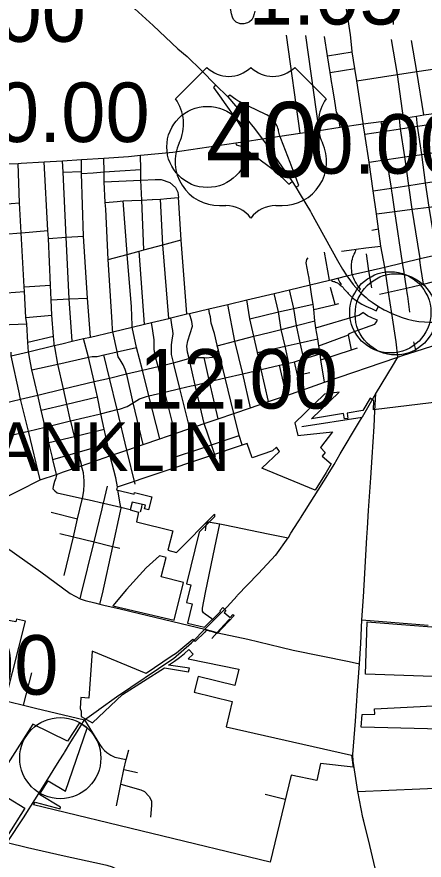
# Model space of a CAD drawing. Extents: x 1659811 to 1934326, y 644115 to 934867.
# Drawn here: x 1811230 to 1818761, y 699875 to 715463 of the extents above; entities that cross this region are included whole.
import ezdxf

# ---------------------------------------------------------------- set-up
doc = ezdxf.new("R2010")
doc.units = 0
for name, color, linetype in [('Default', 7, 'Continuous'), ('GM_X_City_Street', 7, 'Continuous'), ('GM_X_Corporation', 7, 'Continuous'), ('GM_X_County_Road', 7, 'Continuous'), ('GM_X_Interchange_Ramps', 7, 'Continuous'), ('GM_X_Interstate_Route', 7, 'Continuous'), ('GM_X_Township_Road', 7, 'Continuous'), ('GM_X_Township_Text', 7, 'Continuous'), ('GM_X_US_Route', 7, 'Continuous'), ('GM_X_US_Shield', 7, 'Continuous')]:
    doc.layers.add(name, color=color, linetype=linetype)

msp = doc.modelspace()

# ---------------------------------------------------------------- linework, layer by layer
at = {"layer": 'Default'}
for centre in [(1814753, 713058), (1818136, 710001), (1818235, 709964), (1812033, 701761)]:
    msp.add_circle(centre, 750, dxfattribs=at)
at = {"layer": 'GM_X_City_Street'}
for points in [[(1815632, 715569), (1815621, 715518), (1815602, 715455), (1815574, 715407), (1815531, 715370), (1815495, 715351), (1815424, 715332), (1815357, 715336), (1815288, 715363), (1815236, 715416), (1815215, 715459), (1815198, 715518), (1815177, 715654), (1815173, 715717)], [(1817633, 713505), (1817517, 714278), (1817480, 714507), (1817430, 714816), (1817428, 714828), (1817400, 715133), (1817342, 715495), (1817314, 715673)], [(1818194, 715322), (1818207, 715605)], [(1816466, 713313), (1816217, 715127)], [(1816823, 713365), (1816573, 715119)], [(1817054, 714231), (1817022, 714433), (1816973, 714743), (1816916, 715100)], [(1818382, 713593), (1818269, 714396), (1818157, 715046)], [(1818756, 713649), (1818628, 714451), (1818530, 715024)], [(1816973, 714743), (1817430, 714816)], [(1817517, 714278), (1818269, 714396), (1818628, 714451), (1819003, 714510), (1819276, 714553)], [(1817022, 714433), (1817480, 714507)], [(1817175, 713626), (1817170, 713652), (1817139, 713701), (1817108, 713905), (1817058, 714207), (1817054, 714231)], [(1817211, 713422), (1817176, 713623), (1817175, 713626)], [(1818978, 711164), (1818964, 711261), (1818854, 711948), (1818788, 712395), (1818717, 712921), (1818640, 713441), (1818617, 713626)], [(1817819, 712248), (1817745, 712775), (1817666, 713295), (1817636, 713485), (1817633, 713505)], [(1818169, 712211), (1818166, 712232), (1818156, 712299), (1818072, 712824), (1817995, 713343), (1817965, 713531)], [(1817995, 713343), (1818327, 713393), (1818640, 713441), (1819012, 713500), (1819390, 713554)], [(1818748, 710520), (1818701, 710832), (1818679, 710967), (1818688, 710994), (1818646, 711261), (1818537, 711906), (1818478, 712348), (1818404, 712874), (1818327, 713393), (1818303, 713580)], [(1817666, 713295), (1817995, 713343)], [(1817745, 712775), (1818072, 712824), (1818404, 712874), (1818717, 712921), (1819143, 712985), (1819468, 713033), (1819623, 713055)], [(1812589, 709545), (1812534, 710266), (1812465, 711412), (1812427, 712570), (1812425, 712607), (1812422, 712827)], [(1813001, 709686), (1812990, 709821), (1812919, 710977), (1812872, 711906), (1812865, 712034), (1812846, 712414), (1812846, 712596), (1812835, 712849)], [(1813578, 711158), (1813538, 712077), (1813522, 712447), (1813522, 712643), (1813516, 712905)], [(1811465, 709169), (1811457, 709212), (1811446, 709272), (1811432, 709443), (1811413, 709787), (1811395, 709908), (1811369, 710384), (1811369, 710388), (1811364, 710470), (1811309, 711472), (1811279, 712024), (1811256, 712755)], [(1811918, 709434), (1811908, 709555), (1811878, 709951), (1811862, 710233), (1811850, 710504), (1811812, 711369), (1811805, 711515), (1811735, 712781)], [(1812253, 709466), (1812195, 710249), (1812139, 711391), (1812086, 712592), (1812076, 712803)], [(1812086, 712592), (1812425, 712607)], [(1812427, 712570), (1812641, 712579), (1812846, 712596)], [(1812846, 712596), (1813132, 712618), (1813522, 712643)], [(1812846, 712414), (1813522, 712447), (1813788, 712459), (1813867, 712457)], [(1813867, 712457), (1813869, 712457), (1813896, 712457), (1814061, 712399), (1814161, 712310), (1814209, 712220), (1814219, 712122)], [(1818383, 710781), (1818378, 710811), (1818361, 710916), (1818220, 711864), (1818169, 712211)], [(1812865, 712034), (1813082, 712052), (1813086, 712052)], [(1813086, 712052), (1813196, 712061), (1813354, 712068), (1813358, 712068)], [(1813267, 711087), (1813196, 712061)], [(1813358, 712068), (1813538, 712077), (1813733, 712087), (1813735, 712087)], [(1813735, 712087), (1813885, 712094), (1814004, 712104), (1814004, 712104)], [(1814038, 709890), (1813929, 711251), (1813885, 712094)], [(1814004, 712104), (1814219, 712122)], [(1814270, 711335), (1814269, 711340), (1814219, 712122)], [(1817879, 711819), (1818220, 711864), (1818537, 711906), (1818854, 711948), (1819304, 712008), (1819608, 712048), (1819763, 712068)], [(1810647, 711977), (1810973, 712002), (1811279, 712024)], [(1810682, 711426), (1810995, 711449), (1811309, 711472), (1811317, 711473), (1811805, 711515)], [(1811812, 711369), (1812139, 711391), (1812465, 711412)], [(1817794, 711523), (1817917, 711542)], [(1812919, 710977), (1813268, 711071), (1813491, 711131), (1813578, 711158), (1813929, 711251), (1814269, 711340)], [(1814374, 709971), (1814270, 711334), (1814270, 711335)], [(1818037, 710839), (1818361, 710916), (1818688, 710994), (1818992, 711063), (1819364, 711153), (1819710, 711233), (1819868, 711271), (1820152, 711337)], [(1813588, 709784), (1813491, 711131)], [(1817010, 710596), (1816918, 711113)], [(1817235, 711129), (1817470, 711162), (1817504, 711166), (1817680, 711191), (1817962, 711224)], [(1813364, 709756), (1813347, 710101), (1813268, 711071), (1813268, 711073), (1813267, 711084), (1813267, 711087)], [(1816632, 710631), (1816618, 710722), (1816581, 710916), (1816590, 710976), (1816614, 711006)], [(1817739, 710767), (1817698, 711081)], [(1811127, 709200), (1811446, 709272), (1811922, 709387), (1812059, 709420), (1812253, 709466), (1812465, 709515), (1812589, 709545), (1813004, 709643), (1813365, 709730), (1813588, 709784), (1813719, 709816), (1814038, 709890), (1814074, 709898), (1814374, 709971), (1814422, 709982), (1814779, 710066), (1815131, 710149), (1815483, 710232), (1815989, 710351), (1816269, 710420), (1816652, 710508), (1817010, 710596), (1817048, 710605), (1817167, 710633), (1817329, 710673), (1817435, 710700), (1817739, 710767), (1818037, 710839)], [(1817791, 710454), (1817739, 710767)], [(1818458, 710301), (1818455, 710326), (1818437, 710451), (1818383, 710781)], [(1811364, 710470), (1811850, 710504)], [(1816918, 708708), (1816852, 709123), (1816838, 709233), (1816813, 709385), (1816793, 709511), (1816761, 709708), (1816761, 709712), (1816741, 709842), (1816721, 710055), (1816707, 710155), (1816686, 710292), (1816652, 710508), (1816634, 710620), (1816632, 710631)], [(1817937, 710337), (1818104, 710374), (1818437, 710451), (1818590, 710485), (1818748, 710520), (1819056, 710601)], [(1810389, 710321), (1810737, 710343), (1811039, 710362), (1811369, 710384)], [(1816262, 709064), (1816189, 709373), (1816115, 709686), (1816067, 710008), (1815989, 710351)], [(1816537, 709139), (1816471, 709437), (1816401, 709757), (1816352, 710074), (1816269, 710420)], [(1817116, 710146), (1817029, 710461)], [(1811862, 710233), (1812195, 710249), (1812534, 710266)], [(1815886, 708354), (1815750, 708945), (1815678, 709257), (1815610, 709558), (1815538, 709881), (1815483, 710232)], [(1818499, 710002), (1818458, 710301)], [(1815249, 708103), (1815249, 708105), (1815242, 708133), (1815081, 708788), (1814956, 709303), (1814936, 709385), (1814934, 709392), (1814886, 709610), (1814824, 709804), (1814809, 709920), (1814795, 709979), (1814779, 710066)], [(1815553, 708239), (1815406, 708865), (1815263, 709469), (1815131, 710149)], [(1815538, 709881), (1816067, 710008), (1816352, 710074), (1816707, 710155)], [(1816721, 710055), (1817116, 710146), (1817185, 710162)], [(1811395, 709908), (1811878, 709951)], [(1814428, 707853), (1814245, 708592), (1814126, 709070), (1814125, 709077), (1814088, 709224), (1814088, 709298), (1814092, 709398), (1814110, 709530), (1814119, 709598), (1814111, 709663), (1814100, 709725), (1814074, 709898)], [(1814700, 707931), (1814695, 707945), (1814529, 708658), (1814415, 709147), (1814386, 709267), (1814373, 709375), (1814393, 709477), (1814434, 709613), (1814476, 709748), (1814468, 709833), (1814422, 709982)], [(1816761, 709712), (1817552, 709950), (1817583, 709965), (1817625, 710000)], [(1816813, 709385), (1817364, 709584), (1817380, 709609), (1817436, 709636), (1817850, 709782), (1817868, 709807), (1817901, 709859)], [(1817901, 709859), (1817808, 709896), (1817715, 709939), (1817625, 710000)], [(1810424, 709718), (1810770, 709745), (1811095, 709774), (1811413, 709787)], [(1813874, 707663), (1813672, 708457), (1813551, 708933), (1813444, 709353), (1813365, 709730), (1813364, 709756)], [(1814159, 707761), (1813965, 708526), (1813844, 709002), (1813789, 709197), (1813769, 709318), (1813768, 709493), (1813744, 709660), (1813719, 709816)], [(1814936, 709385), (1815263, 709469), (1815610, 709558), (1815897, 709631), (1816115, 709686), (1816401, 709757), (1816741, 709842)], [(1811908, 709555), (1811432, 709443)], [(1813563, 707557), (1813383, 708329), (1813261, 708853), (1813258, 708863), (1813235, 708944), (1813197, 709033), (1813137, 709123), (1813104, 709176), (1813085, 709271), (1813084, 709275), (1813004, 709643), (1813001, 709686)], [(1817415, 709308), (1817364, 709584)], [(1818360, 709201), (1818612, 709282), (1819059, 709426), (1819208, 709477), (1819422, 709552), (1819508, 709582), (1819562, 709600)], [(1812422, 707187), (1812366, 707416), (1812294, 707707), (1812225, 707989), (1812224, 707993), (1812155, 708304), (1812093, 708585), (1811987, 709046), (1811931, 709362), (1811922, 709387), (1811918, 709434)], [(1812952, 707347), (1812904, 707572), (1812847, 707839), (1812784, 708128), (1812718, 708438), (1812659, 708709), (1812657, 708720), (1812554, 709175), (1812465, 709515)], [(1815678, 709257), (1816189, 709373), (1816471, 709437), (1816793, 709511)], [(1818612, 709282), (1818569, 709455)], [(1811277, 708492), (1811127, 709200), (1811123, 709267)], [(1811507, 708936), (1811987, 709046), (1812554, 709175), (1812625, 709186), (1812715, 709187), (1812837, 709215), (1812869, 709222), (1813085, 709271), (1813444, 709353)], [(1814436, 709152), (1814437, 709152), (1814508, 709167), (1814648, 709168), (1814691, 709165), (1814728, 709162), (1814845, 709175), (1814910, 709230), (1814938, 709279), (1814956, 709303)], [(1816538, 709139), (1816838, 709233)], [(1816852, 709123), (1817415, 709308), (1817526, 709345)], [(1809639, 708001), (1810005, 708088), (1810353, 708171), (1810659, 708244), (1810988, 708322), (1811300, 708397), (1811615, 708472), (1812093, 708585), (1812657, 708720), (1812940, 708787), (1813258, 708863), (1813551, 708933), (1813844, 709002), (1814122, 709069), (1814126, 709070), (1814407, 709146), (1814415, 709147), (1814436, 709152)], [(1811889, 707308), (1811886, 707319), (1811833, 707540), (1811820, 707593), (1811753, 707880), (1811681, 708191), (1811615, 708472), (1811507, 708936), (1811465, 709169)], [(1812752, 708120), (1812754, 708121), (1812784, 708128), (1812800, 708132), (1813082, 708203), (1813125, 708214), (1813272, 708259), (1813383, 708329), (1813397, 708338), (1813500, 708400), (1813630, 708447), (1813672, 708457), (1813965, 708526), (1814245, 708592), (1814455, 708641), (1814529, 708658), (1814793, 708721), (1815081, 708788), (1815406, 708865), (1815750, 708945), (1816086, 709025), (1816262, 709064), (1816365, 709088), (1816537, 709139), (1816538, 709139)], [(1813417, 706822), (1813263, 707454), (1813082, 708203), (1812940, 708787), (1812837, 709215)], [(1812952, 707347), (1813263, 707454), (1813563, 707557), (1813874, 707663), (1814159, 707761), (1814428, 707853), (1814695, 707945), (1814952, 708033), (1815242, 708133), (1815553, 708239), (1815886, 708354), (1816215, 708467), (1816485, 708559), (1816918, 708708), (1818255, 709167), (1818275, 709174), (1818360, 709201)], [(1814952, 708033), (1814793, 708721), (1814691, 709165)], [(1816485, 708559), (1816421, 708841), (1816365, 709088)], [(1816215, 708467), (1816086, 709025)], [(1816421, 708841), (1816647, 708890)], [(1811659, 706904), (1811442, 707805), (1811300, 708397), (1811280, 708480), (1811277, 708492)], [(1817851, 708181), (1817869, 708501)], [(1811681, 708191), (1812155, 708304), (1812718, 708438)], [(1810815, 707653), (1810815, 707653), (1811125, 707728), (1811442, 707805), (1811753, 707880), (1812224, 707993), (1812752, 708120)], [(1815395, 707553), (1815343, 707722), (1815249, 708103)], [(1811820, 707593), (1812294, 707707), (1812847, 707839)], [(1814905, 707332), (1814830, 707552), (1814700, 707930), (1814700, 707931)], [(1814611, 707480), (1814611, 707480), (1814830, 707552), (1815343, 707722)], [(1811896, 707279), (1812366, 707416), (1812904, 707572)], [(1814124, 707319), (1814611, 707480)], [(1807606, 707144), (1807927, 707100), (1807937, 707099), (1808229, 707057), (1808515, 707017), (1808525, 707015), (1808870, 706939), (1809249, 706853), (1809618, 706775), (1809997, 706692), (1810006, 706690), (1810372, 706605), (1810720, 706524), (1810820, 706507), (1810850, 706503), (1810880, 706511), (1811659, 706904), (1811963, 707006), (1812095, 707050), (1812428, 707165), (1812952, 707347)], [(1811930, 706699), (1811903, 706731), (1811907, 706787), (1811933, 706879), (1811959, 706945), (1811966, 706993), (1811963, 707006), (1811896, 707279), (1811889, 707308)], [(1813092, 706774), (1813060, 706942), (1812954, 707342), (1812952, 707347)], [(1812472, 706826), (1812472, 706831), (1812475, 706884), (1812462, 707033), (1812428, 707165), (1812422, 707187)], [(1812105, 705139), (1812275, 705853), (1812354, 706187), (1812438, 706542), (1812442, 706563), (1812466, 706699), (1812472, 706826)], [(1812805, 706370), (1812827, 706460), (1812830, 706474), (1812908, 706791)], [(1811930, 706699), (1811975, 706662), (1812442, 706563), (1812564, 706537), (1812830, 706474), (1813154, 706397), (1813328, 706356)], [(1812761, 704608), (1812811, 704798), (1813005, 705673), (1813149, 706323), (1813158, 706379), (1813154, 706397), (1813140, 706460), (1813098, 706715)], [(1813518, 706311), (1813541, 706398), (1813548, 706449)], [(1811863, 706305), (1812354, 706187)], [(1812401, 704708), (1812420, 704788), (1812657, 705759), (1812805, 706370)], [(1810583, 705964), (1810591, 705959), (1810735, 705861), (1811674, 705206), (1812217, 704801), (1812401, 704708), (1812492, 704675), (1812669, 704629), (1812761, 704608), (1812860, 704585)], [(1812026, 705915), (1812275, 705853), (1812657, 705759), (1812976, 705681)], [(1812976, 705681), (1812976, 705681), (1813005, 705673), (1813134, 705642)], [(1812860, 704585), (1813118, 704525), (1813496, 704435), (1814706, 704145)], [(1804587, 704387), (1804884, 704291), (1805626, 704054), (1806239, 703914), (1806558, 703842), (1806871, 703772), (1807204, 703697), (1807447, 703642), (1807701, 703584), (1807975, 703522), (1808509, 703402), (1809302, 703223), (1809996, 703066), (1810269, 703001), (1810590, 702923), (1811352, 702740), (1811574, 702687), (1812483, 702469)], [(1814834, 703972), (1814936, 704083), (1815066, 704222), (1815164, 704327), (1815165, 704328)], [(1814706, 704145), (1814820, 704114), (1814908, 704090)], [(1811352, 702740), (1811508, 703338)], [(1812483, 702469), (1812756, 702022), (1812804, 701958), (1812853, 701903), (1812896, 701866), (1812969, 701816), (1813044, 701781), (1813249, 701734)], [(1813255, 701754), (1813255, 701755), (1813300, 701915)], [(1813070, 700880), (1813154, 701278), (1813210, 701548), (1813249, 701734), (1813255, 701754)], [(1813210, 701548), (1813458, 701496)], [(1813154, 701278), (1813521, 701177), (1813587, 701143), (1813679, 701054), (1813717, 700972), (1813722, 700886), (1813699, 700672)], [(1815824, 701094), (1816193, 701004)]]:
    msp.add_lwpolyline(points, dxfattribs=at)
at = {"layer": 'GM_X_Corporation'}
for points in [[(1819092, 708352), (1817822, 708202), (1817832, 708367), (1817760, 708412), (1817629, 708188), (1817336, 708139), (1817353, 708041), (1817289, 708030), (1817272, 708129), (1816681, 708030), (1817192, 708523), (1816917, 708489), (1816373, 707961), (1816428, 707722), (1817066, 707795), (1816842, 707501), (1816930, 707412), (1816875, 707341), (1817042, 707199), (1816947, 707038), (1816744, 706716), (1815762, 707118), (1816088, 707429), (1816030, 707511), (1815960, 707439), (1815580, 707312), (1815491, 707579), (1813086, 706772), (1813074, 706723), (1813398, 706643), (1813406, 706672), (1813726, 706592), (1813666, 706350), (1813590, 706369), (1813606, 706435), (1813362, 706495), (1813325, 706348), (1813481, 706306), (1813440, 706128), (1814111, 705962), (1814022, 705602), (1814180, 705562), (1814886, 706270), (1814886, 706220), (1814603, 705937), (1814368, 704985), (1814446, 704966), (1814364, 704636), (1814471, 704610), (1814383, 704254), (1814698, 704179), (1814998, 704471), (1814982, 704484), (1815040, 704544), (1815097, 704490), (1815065, 704455), (1815175, 704358), (1815225, 704413), (1815247, 704398), (1814936, 704064), (1814865, 704088), (1814791, 704110), (1814763, 704120), (1814745, 704123), (1814735, 704122), (1814726, 704116), (1814704, 704092), (1814528, 703915), (1814483, 703955), (1814264, 703770), (1814180, 703701), (1814086, 703637), (1813620, 703324), (1812622, 703736), (1812562, 702871), (1812412, 702879), (1812402, 702679), (1812419, 702629), (1812417, 702529), (1812631, 702416), (1813185, 702940), (1813958, 703430), (1814405, 703357), (1814424, 703425), (1814031, 703479), (1814142, 703554), (1814240, 703621), (1814330, 703695), (1814408, 703767), (1814491, 703683), (1814400, 703594), (1815333, 703405), (1815260, 703105), (1814580, 703270), (1814509, 702979), (1815214, 702808), (1815100, 702340), (1817416, 701818), (1817446, 701593), (1816842, 701664), (1816776, 701348), (1816300, 701446), (1815911, 699839), (1811537, 700898), (1811567, 700947), (1812032, 700824), (1812038, 700853), (1811647, 701087), (1811808, 701344), (1812132, 701149), (1812531, 702316), (1812386, 702414), (1812165, 702073), (1811523, 702388), (1810768, 701206), (1811377, 700837), (1811050, 700319)], [(1819273, 703255), (1817674, 703310), (1817708, 704278), (1821130, 704013)], [(1820298, 702267), (1817599, 702331), (1817613, 702570), (1817847, 702574), (1817842, 702674), (1820013, 702784)]]:
    msp.add_lwpolyline(points, dxfattribs=at)
for points in [[(1813003, 704579), (1814139, 704311), (1814312, 705010), (1813900, 705112), (1813989, 705471), (1813865, 705503), (1813622, 705278), (1813256, 704881)], [(1809943, 703115), (1810427, 703000), (1810462, 703147), (1810598, 703115), (1810574, 702964), (1811023, 702855), (1811391, 704290), (1811225, 704327), (1811212, 704279), (1810263, 704456)]]:
    msp.add_lwpolyline(points, close=True, dxfattribs=at)
at = {"layer": 'GM_X_County_Road'}
for points in [[(1817938, 699386), (1817759, 700149), (1817644, 700598), (1817629, 700665), (1817533, 701143), (1817450, 701707), (1817443, 701825), (1817489, 702443), (1817530, 703011), (1817543, 703177), (1817566, 703505), (1817591, 703881), (1817611, 704316), (1817637, 704743), (1817662, 705171), (1817682, 705514), (1817701, 705841), (1817711, 706013), (1817734, 706340), (1817775, 706942), (1817801, 707326), (1817835, 707892), (1817851, 708181)], [(1817611, 704316), (1818834, 704221)], [(1817533, 701143), (1818679, 701196), (1820412, 701266), (1820415, 701266)], [(1811053, 700199), (1811425, 700111), (1812105, 699958), (1812813, 699801), (1812894, 699783), (1812991, 699750), (1813240, 699627), (1813370, 699562), (1813638, 699430), (1813850, 699359), (1814253, 699302), (1814675, 699256), (1814681, 699255), (1815117, 699166), (1815138, 699162)]]:
    msp.add_lwpolyline(points, dxfattribs=at)
at = {"layer": 'GM_X_Interchange_Ramps'}
for points in [[(1814906, 714207), (1814863, 714158), (1814977, 714002), (1815095, 713835), (1815259, 713601), (1815313, 713520), (1815350, 713460), (1815369, 713429), (1815382, 713402), (1815394, 713372), (1815402, 713347), (1815409, 713321), (1815415, 713293), (1815419, 713256), (1815423, 713231), (1815435, 713201), (1815449, 713162)], [(1816095, 713258), (1816079, 713305), (1816071, 713356), (1816066, 713377), (1816058, 713405), (1816048, 713431), (1816036, 713457), (1816021, 713486), (1816005, 713512), (1815984, 713539), (1815964, 713562), (1815942, 713585), (1815914, 713609), (1815879, 713634), (1815851, 713650), (1815832, 713660), (1815513, 713811), (1815472, 713829), (1815429, 713850), (1815391, 713870), (1815352, 713893), (1815319, 713913), (1815281, 713938), (1815169, 714017), (1815133, 713987)], [(1815281, 713137), (1815287, 713096), (1815356, 713076), (1815386, 713064), (1815412, 713052), (1815442, 713035), (1815468, 713016), (1815497, 712993), (1815868, 712716), (1815969, 712640), (1816055, 712572), (1816085, 712543), (1816108, 712521), (1816130, 712500), (1816156, 712475), (1816181, 712450), (1816203, 712428), (1816224, 712407), (1816258, 712372), (1816322, 712420)], [(1815449, 713162), (1815456, 713115), (1815462, 713092), (1815471, 713068), (1815482, 713047), (1815492, 713031), (1815510, 713010), (1815497, 712993)], [(1816388, 712313), (1816444, 712346), (1816409, 712443), (1816383, 712510), (1816359, 712577), (1816342, 712626), (1816285, 712770), (1816112, 713213), (1816095, 713258)], [(1817551, 710401), (1817586, 710432), (1817561, 710464), (1817543, 710486), (1817524, 710511), (1817508, 710535), (1817488, 710569), (1817473, 710597), (1817460, 710626), (1817450, 710651), (1817441, 710678), (1817435, 710700), (1817433, 710706), (1817426, 710738), (1817421, 710773), (1817417, 710809), (1817416, 710848), (1817418, 710890), (1817423, 710928), (1817427, 710951), (1817434, 710984), (1817444, 711018), (1817455, 711051), (1817467, 711078), (1817483, 711110), (1817494, 711130), (1817501, 711142), (1817504, 711166)], [(1817167, 710633), (1817171, 710613), (1817182, 710590), (1817195, 710567), (1817204, 710551), (1817214, 710535), (1817226, 710515), (1817210, 710505)], [(1817048, 710605), (1817052, 710579), (1817086, 710573), (1817102, 710569), (1817123, 710561), (1817142, 710553), (1817156, 710545), (1817171, 710536), (1817186, 710525), (1817210, 710505), (1817244, 710477), (1817261, 710460), (1817272, 710448), (1817279, 710438), (1817295, 710418), (1817310, 710400), (1817324, 710384), (1817341, 710365), (1817356, 710348), (1817373, 710332), (1817392, 710313), (1817417, 710290), (1817439, 710270), (1817460, 710253), (1817480, 710237), (1817504, 710220), (1817527, 710204), (1817551, 710188), (1817578, 710171), (1817612, 710152), (1817647, 710133), (1817684, 710115), (1817726, 710097), (1817799, 710063), (1817877, 710031), (1817920, 710107)]]:
    msp.add_lwpolyline(points, dxfattribs=at)
at = {"layer": 'GM_X_Interstate_Route'}
for points in [[(1812533, 716247), (1812678, 716161), (1812775, 716100), (1812908, 716002), (1813077, 715880), (1813183, 715790), (1813411, 715611), (1813749, 715304), (1814209, 714873), (1814376, 714732), (1814645, 714472), (1814906, 714207), (1815133, 713987), (1815483, 713571), (1815623, 713399), (1815769, 713210)], [(1815769, 713210), (1815857, 713086)], [(1815857, 713086), (1815971, 712926), (1816322, 712420), (1816388, 712313), (1816469, 712178)], [(1816469, 712178), (1816660, 711864)], [(1816660, 711864), (1816675, 711839), (1817158, 710962), (1817251, 710800), (1817329, 710673)], [(1817329, 710673), (1817397, 710581), (1817448, 710516), (1817551, 710401)], [(1817551, 710401), (1817609, 710344), (1817689, 710273), (1817728, 710241), (1817799, 710189), (1817920, 710107), (1818025, 710047), (1818064, 710028)], [(1818064, 710028), (1818162, 709980), (1818354, 709903), (1818455, 709874), (1818556, 709850), (1818660, 709834), (1818871, 709818), (1819020, 709821), (1819151, 709837), (1819311, 709860), (1819429, 709891)]]:
    msp.add_lwpolyline(points, dxfattribs=at)
at = {"layer": 'GM_X_Township_Road'}
for points in [[(1816497, 707890), (1817613, 708061)], [(1814716, 705961), (1814731, 706059), (1814741, 706105), (1814758, 706125), (1814774, 706131), (1814874, 706112)], [(1814874, 706112), (1814877, 706112), (1814983, 706093), (1815077, 706075), (1815878, 705908), (1816246, 705832)], [(1814864, 704304), (1814834, 704335), (1814710, 704419), (1814680, 704444), (1814663, 704480), (1814664, 704535), (1814721, 704822), (1814888, 705652), (1814983, 706093)], [(1814908, 704090), (1814936, 704083), (1814945, 704080), (1815500, 703957), (1816111, 703813), (1816342, 703758), (1817376, 703545), (1817566, 703505)]]:
    msp.add_lwpolyline(points, dxfattribs=at)
at = {"layer": 'GM_X_US_Route'}
for points in [[(1816095, 713258), (1816466, 713313), (1816823, 713365), (1817211, 713422), (1817636, 713485), (1817965, 713531), (1818303, 713580), (1818382, 713593), (1818617, 713626), (1818756, 713649), (1818984, 713684), (1819116, 713703), (1819365, 713741), (1819403, 713749), (1819805, 713806), (1820123, 713854), (1820280, 713876)], [(1811311, 712758), (1811735, 712781), (1812076, 712803), (1812422, 712827), (1812835, 712849), (1813292, 712880), (1813516, 712905), (1814114, 712964), (1815281, 713137)], [(1815281, 713137), (1815281, 713137), (1815449, 713162), (1815769, 713210)], [(1815769, 713210), (1816095, 713258)], [(1807602, 712555), (1807934, 712562), (1808231, 712580), (1808266, 712582), (1808530, 712604), (1808612, 712609), (1808913, 712626), (1808960, 712629), (1809119, 712631), (1809250, 712639), (1809333, 712644), (1809624, 712668), (1809728, 712670), (1809970, 712683), (1810073, 712689), (1810276, 712704), (1810424, 712716), (1810631, 712720), (1810706, 712721), (1810942, 712741), (1810997, 712744), (1811256, 712755), (1811311, 712758)], [(1817819, 712248), (1818156, 712299), (1818478, 712348), (1818788, 712395), (1819237, 712464), (1819542, 712510), (1819973, 712575)], [(1818162, 709980), (1818104, 710374), (1818037, 710839), (1817962, 711224), (1817917, 711542), (1817879, 711819), (1817819, 712248)], [(1818275, 709174), (1818245, 709454), (1818162, 709980)], [(1818174, 709005), (1818275, 709174)], [(1817843, 708455), (1817869, 708501), (1817881, 708521), (1818173, 709005), (1818174, 709005)], [(1815116, 704560), (1815303, 704762), (1815311, 704771), (1815687, 705163), (1815699, 705175), (1816014, 705510), (1816020, 705515), (1816246, 705832), (1816253, 705842), (1816299, 705917), (1816431, 706128), (1816467, 706185), (1816473, 706194), (1816980, 706997), (1816989, 707012), (1817095, 707189), (1817211, 707385), (1817548, 707952), (1817613, 708061), (1817619, 708072), (1817842, 708455), (1817843, 708455)], [(1815043, 704484), (1815087, 704528), (1815116, 704560)], [(1814706, 704145), (1814864, 704304), (1815043, 704484)], [(1814482, 703914), (1814486, 703918), (1814706, 704145)], [(1812744, 702658), (1813075, 702896), (1814114, 703595), (1814126, 703603), (1814460, 703892), (1814482, 703914)], [(1812346, 702250), (1812483, 702469), (1812742, 702656), (1812744, 702658)], [(1812102, 701855), (1812108, 701866), (1812230, 702063), (1812346, 702250)], [(1811362, 700675), (1811384, 700709), (1811562, 700989), (1811803, 701374), (1811901, 701532), (1812011, 701708), (1812102, 701855)], [(1810720, 699682), (1810774, 699768), (1811053, 700199), (1811362, 700675)]]:
    msp.add_lwpolyline(points, dxfattribs=at)
at = {"layer": 'GM_X_US_Shield'}
for p, q in [((1814745, 714528), (1814165, 713948)), ((1816949, 713948), (1816369, 714528)), ((1814977, 711976), (1815093, 711976)), ((1816021, 711976), (1816137, 711976))]:
    msp.add_line(p, q, dxfattribs=at)
for centre, radius, start, end in [((1815151, 714943), 580, 225.573, 314.427), ((1815963, 714943), 580, 225.573, 314.427), ((1813499, 713483), 812, 334.5471, 35.0009), ((1817614, 713483), 812, 144.9991, 205.4529), ((1814968, 712788), 812, 154.8319, 270.6383), ((1816146, 712788), 812, 269.3617, 25.1681), ((1815093, 711396), 580, 36.8699, 90), ((1816021, 711396), 580, 90, 143.1301)]:
    msp.add_arc(centre, radius, start, end, dxfattribs=at)

# ---------------------------------------------------------------- texts
at = {"layer": 'Default'}
for s, p in [('1.05', (1815518, 715321)), ('10.00', (1808826, 715002)), ('10.00', (1810005, 713149)), ('0.00', (1816639, 712564)), ('12.00', (1813486, 708222)), ('10.00', (1808319, 702934))]:
    msp.add_text(s, height=1100, dxfattribs=at).set_placement(p)
at = {"layer": 'GM_X_Township_Text'}
msp.add_text('FRANKLIN', height=900, rotation=0, dxfattribs=at).set_placement((1809216, 707067))
at = {"layer": 'GM_X_US_Shield'}
msp.add_text('40', height=1392.2, dxfattribs=at).set_placement((1814721, 712498))

doc.saveas('drawing.dxf')
